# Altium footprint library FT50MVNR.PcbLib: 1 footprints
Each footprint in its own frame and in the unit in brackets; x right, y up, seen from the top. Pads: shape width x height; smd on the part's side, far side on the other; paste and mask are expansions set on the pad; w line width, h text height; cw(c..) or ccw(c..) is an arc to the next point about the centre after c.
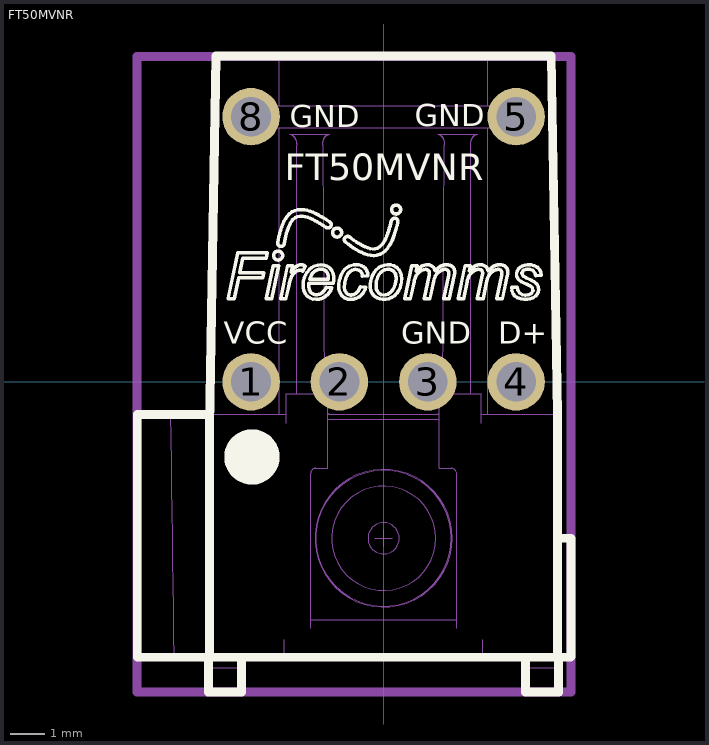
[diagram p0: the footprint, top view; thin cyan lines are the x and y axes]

## FT50MVNR [mil] "50 MBd Vertical Package Non-Inverting TTL"
height 744.09
pads (6):
  round 65 hole 45: 1(-150,0) 2(-50,0) 3(50,0) 4(150,0) 5(150,300) 8(-150,300)
Top Overlay:
  drawing of 818 lines, arcs and shapes, not listed
  text "GND" at -106,288 h25
  text "GND" at 35,289 h25
  text "FT50MVNR" at -112,228 h30
  text "D+" at 129.92,43.31 h25
  text "GND" at 19.68,43.31 h25
  text "VCC" at -181.1,43.31 h25
Mechanical 2:
  lines w10: -279,-351 212,-351 212,368 -279,368 -279,-351
Mechanical 19:
  drawing of 829 lines, arcs and shapes, not listed
3D body "Vertical Redlink Connector.stp": height 745.89, standoff -128.11, extent -278.74,-354.01 211.81,365.67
